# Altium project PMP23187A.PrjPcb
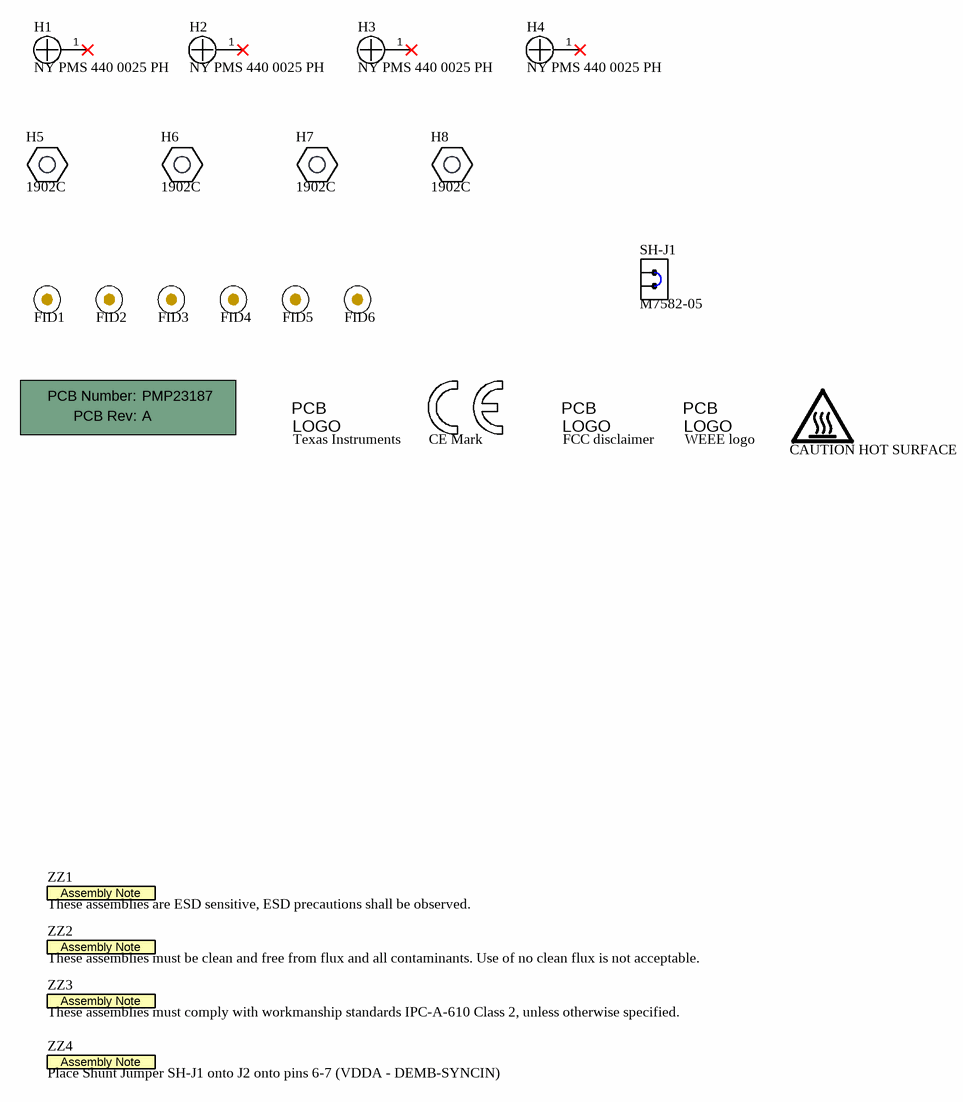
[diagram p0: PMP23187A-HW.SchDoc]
CopyrightYear: 2021; PCB_Layout: K Nielson; PCB_Rev: A; PRJ_Customer: Public Release; PRJ_Engineer: T Hegarty; PRJ_Number: PMP23187; PRJ_Title: LM5143Q-250W; SCH_Rev: A; TechSupport: http://www.ti.com/support; TID: N/A
2 sheets, 122 parts. Net scope: global (net labels, ports and power ports of the same name join across sheets).
Board file: PMP23187A.PcbDoc
Sheets:
  PMP23187A-HW.SchDoc
  PMP23187A-SCH.SchDoc

## Sheet PMP23187A-HW.SchDoc: LM5143Q-250W Hardware
size 431 x 279 mm; Date: Not shown in title block; ApprovedBy: Not shown in title block; CheckedBy: Not shown in title block; Author: Not shown in title block; CompanyName: Not shown in title block; DrawnBy: K Nielson; Engineer: Not shown in title block; Organization: Not shown in title block; Address1: Not shown in title block; Address2: Not shown in title block; Address3: Not shown in title block; Address4: Not shown in title block; DocumentNumber: 1; Revision: Use project parameter SCH_Rev; SheetNumber: 1; SheetTotal: 2; PageSetup: Record=PageOptions¦CenterHorizontal=True¦CenterVertical=True¦PrintScale=1.00¦XCorrection=1.00¦YCorrection=1.00¦PrintKind=0¦BorderSize=5000000¦LeftOffset=0¦BottomOffset=0¦Orientation=2¦PaperLength=1000¦PaperWidth=1000¦Scale=100¦PaperSource=15¦PrintQuality=600¦MediaType=1¦DitherType=10¦PaperKind=Letter¦PrintScaleMode=1

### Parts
!PCB1  Printed Circuit Board  (value not drawn)  (mechanical)
FID1  Fiducial  [Fiducial10-20]  (value not drawn)
FID2  Fiducial  [Fiducial10-20]  (value not drawn)
FID3  Fiducial  [Fiducial10-20]  (value not drawn)
FID4  Fiducial  [Fiducial10-20]  (value not drawn)
FID5  Fiducial  [Fiducial10-20]  (value not drawn)
FID6  Fiducial  [Fiducial10-20]  (value not drawn)
H1  NY PMS 440 0025 PH  [NY PMS 440 0025 PH]
H2  NY PMS 440 0025 PH  [NY PMS 440 0025 PH]
H3  NY PMS 440 0025 PH  [NY PMS 440 0025 PH]
H4  NY PMS 440 0025 PH  [NY PMS 440 0025 PH]
H5  1902C  [Keystone_1902C]
H6  1902C  [Keystone_1902C]
H7  1902C  [Keystone_1902C]
H8  1902C  [Keystone_1902C]
Logo1  CE Mark  [CE_Mark_5mm]  (no BOM)
Logo2  CAUTION HOT SURFACE  [IEC_HotSurface_Small]  (no BOM)
Logo3  Texas Instruments  [TI_Stacked_Overlay_Small]  (no BOM)
Logo4  FCC disclaimer  [FCC_disclaimer]  (no BOM)
Logo5  WEEE logo  [WEEE_Minimum]  (no BOM)
SH-J1  M7582-05  [Harwin_M7582-05]
ZZ1  These assemblies are ESD sensitive, ESD precautions shall be observed.  [AssemblyNote]  (no BOM)
ZZ2  These assemblies must be clean and free from flux and all contaminants. Use of no clean flux is not acceptable.  [AssemblyNote]  (no BOM)
ZZ3  These assemblies must comply with workmanship standards IPC-A-610 Class 2, unless otherwise specified.  [AssemblyNote]  (no BOM)
ZZ4  Place Shunt Jumper SH-J1 onto J2 onto pins 6-7 (VDDA - DEMB-SYNCIN)  [AssemblyNote]  (no BOM)

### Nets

Not connected (* = marked no-connect by the designer): H1 1*; H2 1*; H3 1*; H4 1*

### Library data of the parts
!PCB1 = CMP-0003618-2: Manufacturer: Any; PartNumber: PMP23187
FID1-FID6 = CMP-0077181-1: Fiducial mark.  There is nothing to buy or mount.
H1-H4 = CMP-0003617-1: Machine Screw, Round, #4-40 x 1/4, Nylon, Philips panhead; Manufacturer: B&F Fastener Supply; CompType: Hardware
H5-H8 = CMP-0003610-1: Standoff, Hex, 0.5"L #4-40 Nylon; Manufacturer: Keystone; CompType: Hardware
Logo1 = CMP-0074844-1: SymbolCreator: a0412235
Logo2 = CMP-0074837-2: IEC 61010-1 Hot Surface Warning; Manufacturer: Texas Instruments; SymbolCreator: a0412235; AEC Category: Q200; CompType: IC
Logo3 = CMP-0074838-1: Texas Instrument Corporate Signature; SymbolCreator: a0412235; Lib Reference: TI_Logo; Library Reference: Logo
Logo4 = CMP-0074847-1: FCC_disclaimer; Library Reference: Logo
Logo5 = CMP-0074769-1
SH-J1 = CMP-0078738-1: Single Operation 2.54mm Pitch Open Top Jumper Socket; Manufacturer: Harwin; CompType: Shunt
ZZ1 = CMP-0077236-1
ZZ2 = CMP-0077237-1
ZZ3 = CMP-0077238-1
ZZ4 = CMP-0077238-1: Place Shunt Jumper SH-J1 onto J2 pins VDDA - DEMB

## Sheet PMP23187A-SCH.SchDoc: LM5143Q-250W Schematic
size 431 x 279 mm; Date: Not shown in title block; ApprovedBy: Not shown in title block; CheckedBy: Not shown in title block; Author: Not shown in title block; CompanyName: Not shown in title block; DrawnBy: K Nielson; Engineer: Not shown in title block; Organization: Not shown in title block; Address1: Not shown in title block; Address2: Not shown in title block; Address3: Not shown in title block; Address4: Not shown in title block; DocumentNumber: 2; Revision: Use project parameter SCH_Rev; SheetNumber: 2; SheetTotal: 2; PageSetup: Record=PageOptions¦CenterHorizontal=True¦CenterVertical=True¦PrintScale=0.96¦XCorrection=1.00¦YCorrection=1.00¦PrintKind=0¦BorderSize=5000000¦LeftOffset=0¦BottomOffset=0¦Orientation=2¦PaperLength=1000¦PaperWidth=1000¦Scale=100¦PaperSource=7¦PrintQuality=600¦MediaType=1¦DitherType=10¦PaperKind=11" x 17"¦PrintScaleMode=1
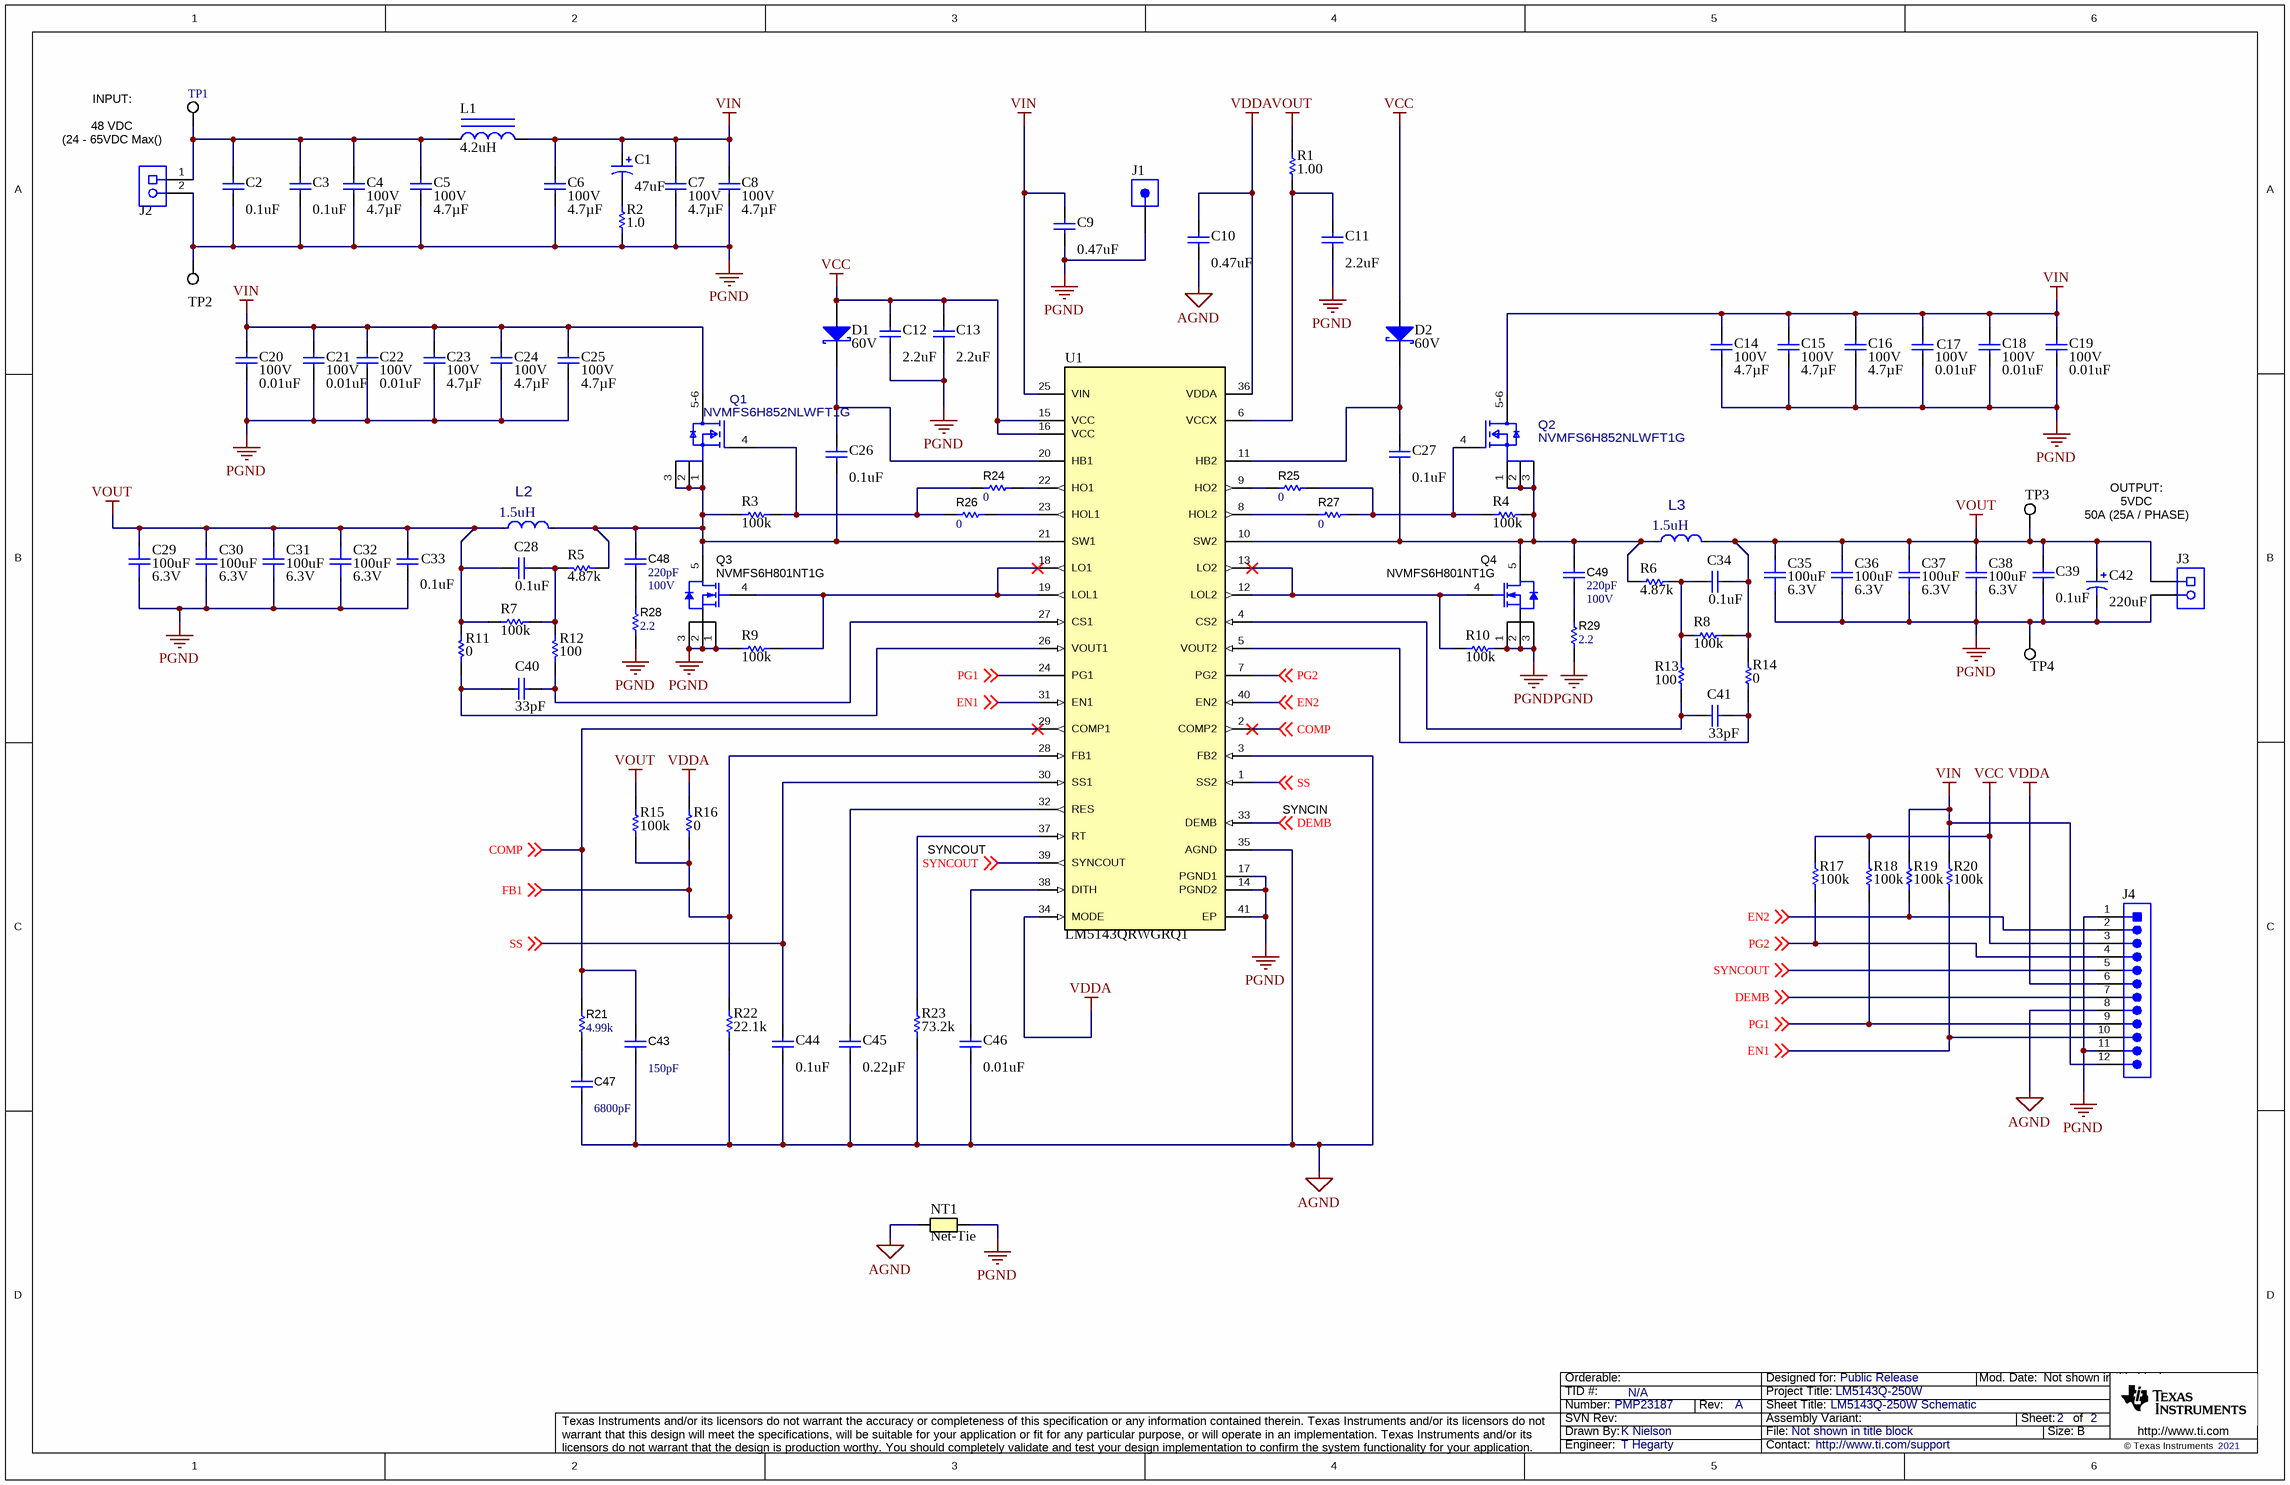
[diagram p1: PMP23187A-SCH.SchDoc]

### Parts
C1  ValueDisplayed: 47uF  [SM_RADIAL_G]  (hidden comment: EEE-FC1H470P)
C2  ValueDisplayed: 0.1uF  [0805_HV]  (hidden comment: C0805C104K1RACTU)
C3  ValueDisplayed: 0.1uF  [0805_HV]  (hidden comment: C0805C104K1RACTU)
C4  VDC_V: 100V  ValueDisplayed: 4.7µF  [1210_220]  (hidden comment: GCM32DC72A475KE02L)
C5  VDC_V: 100V  ValueDisplayed: 4.7µF  [1210_220]  (hidden comment: GCM32DC72A475KE02L)
C6  VDC_V: 100V  ValueDisplayed: 4.7µF  [1210_220]  (hidden comment: GCM32DC72A475KE02L)
C7  VDC_V: 100V  ValueDisplayed: 4.7µF  [1210_220]  (hidden comment: GCM32DC72A475KE02L)
C8  VDC_V: 100V  ValueDisplayed: 4.7µF  [1210_220]  (hidden comment: GCM32DC72A475KE02L)
C9  ValueDisplayed: 0.47uF  [0805L]  (hidden comment: GRM21BR72A474KA73L)
C10  ValueDisplayed: 0.47uF  [0603L]  (hidden comment: GCM188R71C474KA55D)
C11  ValueDisplayed: 2.2uF  [0603L]  (hidden comment: GRM188R71A225KE15D)
C12  ValueDisplayed: 2.2uF  [0603L]  (hidden comment: GRM188R71A225KE15D)
C13  ValueDisplayed: 2.2uF  [0603L]  (hidden comment: GRM188R71A225KE15D)
C14  VDC_V: 100V  ValueDisplayed: 4.7µF  [1210_220]  (hidden comment: GCM32DC72A475KE02L)
C15  VDC_V: 100V  ValueDisplayed: 4.7µF  [1210_220]  (hidden comment: GCM32DC72A475KE02L)
C16  VDC_V: 100V  ValueDisplayed: 4.7µF  [1210_220]  (hidden comment: GCM32DC72A475KE02L)
C17  VDC_V: 100V  ValueDisplayed: 0.01uF  [0402S]  (hidden comment: CGA2B3X7S2A103K050BB)
C18  VDC_V: 100V  ValueDisplayed: 0.01uF  [0402S]  (hidden comment: CGA2B3X7S2A103K050BB)
C19  VDC_V: 100V  ValueDisplayed: 0.01uF  [0402S]  (hidden comment: CGA2B3X7S2A103K050BB)
C20  VDC_V: 100V  ValueDisplayed: 0.01uF  [0402S]  (hidden comment: CGA2B3X7S2A103K050BB)
C21  VDC_V: 100V  ValueDisplayed: 0.01uF  [0402S]  (hidden comment: CGA2B3X7S2A103K050BB)
C22  VDC_V: 100V  ValueDisplayed: 0.01uF  [0402S]  (hidden comment: CGA2B3X7S2A103K050BB)
C23  VDC_V: 100V  ValueDisplayed: 4.7µF  [1210_220]  (hidden comment: GCM32DC72A475KE02L)
C24  VDC_V: 100V  ValueDisplayed: 4.7µF  [1210_220]  (hidden comment: GCM32DC72A475KE02L)
C25  VDC_V: 100V  ValueDisplayed: 4.7µF  [1210_220]  (hidden comment: GCM32DC72A475KE02L)
C26  ValueDisplayed: 0.1uF  [0603L]  (hidden comment: CGA3E2X7R1E104K080AA)
C27  ValueDisplayed: 0.1uF  [0603L]  (hidden comment: CGA3E2X7R1E104K080AA)
C28  ValueDisplayed: 0.1uF  [0603L]  (hidden comment: CGA3E2X7R1E104K080AA)
C29  ValueDisplayed: 100uF  VDC_V: 6.3V  [FP-GRM32EE70J107ME15L_1210-MFG]  (hidden comment: GRM32EE70J107ME15L)
C30  ValueDisplayed: 100uF  VDC_V: 6.3V  [FP-GRM32EE70J107ME15L_1210-MFG]  (hidden comment: GRM32EE70J107ME15L)
C31  ValueDisplayed: 100uF  VDC_V: 6.3V  [FP-GRM32EE70J107ME15L_1210-MFG]  (hidden comment: GRM32EE70J107ME15L)
C32  ValueDisplayed: 100uF  VDC_V: 6.3V  [FP-GRM32EE70J107ME15L_1210-MFG]  (hidden comment: GRM32EE70J107ME15L)
C33  ValueDisplayed: 0.1uF  [0603L]  (hidden comment: GRM188R72A104KA35D)
C34  ValueDisplayed: 0.1uF  [0603L]  (hidden comment: CGA3E2X7R1E104K080AA)
C35  ValueDisplayed: 100uF  VDC_V: 6.3V  [FP-GRM32EE70J107ME15L_1210-MFG]  (hidden comment: GRM32EE70J107ME15L)
C36  ValueDisplayed: 100uF  VDC_V: 6.3V  [FP-GRM32EE70J107ME15L_1210-MFG]  (hidden comment: GRM32EE70J107ME15L)
C37  ValueDisplayed: 100uF  VDC_V: 6.3V  [FP-GRM32EE70J107ME15L_1210-MFG]  (hidden comment: GRM32EE70J107ME15L)
C38  ValueDisplayed: 100uF  VDC_V: 6.3V  [FP-GRM32EE70J107ME15L_1210-MFG]  (hidden comment: GRM32EE70J107ME15L)
C39  ValueDisplayed: 0.1uF  [0603L]  (hidden comment: CGA3E2X7R1E104K080AA)
C40  ValueDisplayed: 33pF  [0603L]  (hidden comment: 06031A330JAT2A)
C41  ValueDisplayed: 33pF  [0603L]  (hidden comment: 06031A330JAT2A)
C42  ValueDisplayed: 220uF  [7343-31]  (hidden comment: T598D227M010ATE025)
C43  ValueDisplayed: 150pF  [0603L]  (hidden comment: 06035A151JAT2A)
C44  ValueDisplayed: 0.1uF  [0603L]  (hidden comment: CGA3E2X7R1E104K080AA)
C45  ValueDisplayed: 0.22µF  [0603L]  (hidden comment: CL10B224KO8VPNC)
C46  ValueDisplayed: 0.01uF  [0603L]  (hidden comment: GRM188R72A103KA01D)
C47  ValueDisplayed: 6800pF  [0603L]  (hidden comment: GRM1885C1H682JA01D)
C48  Cap_F: 220pF  VDC_V: 100V  [0603_HV]  (hidden comment: 06031C221KAT2A)
C49  Cap_F: 220pF  VDC_V: 100V  [0603_HV]  (hidden comment: 06031C221KAT2A)
D1  60V  [SOD-323F]
D2  60V  [SOD-323F]
J1  1040  [CONN_1040]  (value not drawn)
J2  1714971  [Phoenix_1714971]  (value not drawn)
J3  EM292902-UL  [Eaton_EM292902]  (value not drawn)
J4  TSW-112-07-G-S  [TSW-112-07-G-S]  (value not drawn)
L1  ValueDisplayed: 4.2uH  [WE-HC6]  (hidden comment: 744325420)
L2  value 1.5uH  [FP-VCUD128T-1R5M58_SMD2-MFG]  (hidden comment: VCUD128T-1R5M58)
L3  value 1.5uH  [FP-VCUD128T-1R5M58_SMD2-MFG]  (hidden comment: VCUD128T-1R5M58)
NT1  Net-Tie  [Net-Tie_10mil]  (net tie, no BOM)
Q1  NVMFS6H852NLWFT1G  [FP-NVMFS6H852NLWFT1G_DFN5-MFG]
Q2  NVMFS6H852NLWFT1G  [FP-NVMFS6H852NLWFT1G_DFN5-MFG]
Q3  NVMFS6H801NT1G  [SO-8FL]
Q4  NVMFS6H801NT1G  [SO-8FL]
R1  ValueDisplayed: 1.00  [0603L]  (hidden comment: RC0603FR-071RL)
R2  ValueDisplayed: 1.0  [1206]  (hidden comment: CRCW12061R00JNEA)
R3  ValueDisplayed: 100k  [0603L]  (hidden comment: CRCW0603100KFKEA)
R4  ValueDisplayed: 100k  [0603L]  (hidden comment: CRCW0603100KFKEA)
R5  ValueDisplayed: 4.87k  [0603L]  (hidden comment: RC0603FR-074K87L)
R6  ValueDisplayed: 4.87k  [0603L]  (hidden comment: RC0603FR-074K87L)
R7  ValueDisplayed: 100k  [0603L]  (hidden comment: CRCW0603100KFKEA)
R8  ValueDisplayed: 100k  [0603L]  (hidden comment: CRCW0603100KFKEA)
R9  ValueDisplayed: 100k  [0603L]  (hidden comment: CRCW0603100KFKEA)
R10  ValueDisplayed: 100k  [0603L]  (hidden comment: CRCW0603100KFKEA)
R11  ValueDisplayed: 0  [0603L]  (hidden comment: CRCW06030000Z0EA)
R12  ValueDisplayed: 100  [0603L]  (hidden comment: CRCW0603100RFKEA)
R13  ValueDisplayed: 100  [0603L]  (hidden comment: CRCW0603100RFKEA)
R14  ValueDisplayed: 0  [0603L]  (hidden comment: CRCW06030000Z0EA)
R15  ValueDisplayed: 100k  [0603L]  (hidden comment: CRCW0603100KFKEA)
R16  ValueDisplayed: 0  [0603L]  (hidden comment: CRCW06030000Z0EA)
R17  ValueDisplayed: 100k  [0603L]  (hidden comment: CRCW0603100KFKEA)
R18  ValueDisplayed: 100k  [0603L]  (hidden comment: CRCW0603100KFKEA)
R19  ValueDisplayed: 100k  [0603L]  (hidden comment: CRCW0603100KFKEA)
R20  ValueDisplayed: 100k  [0603L]  (hidden comment: CRCW0603100KFKEA)
R21  ValueDisplayed: 4.99k  [0603L]  (hidden comment: RC0603FR-074K99L)
R22  ValueDisplayed: 22.1k  [0603L]  (hidden comment: CRCW060322K1FKEA)
R23  ValueDisplayed: 73.2k  [0603L]  (hidden comment: RC0603FR-0773K2L)
R24  ValueDisplayed: 0  [0402L]  (hidden comment: ERJ-2GE0R00X)
R25  ValueDisplayed: 0  [0402L]  (hidden comment: ERJ-2GE0R00X)
R26  ValueDisplayed: 0  [0402L]  (hidden comment: ERJ-2GE0R00X)
R27  ValueDisplayed: 0  [0402L]  (hidden comment: ERJ-2GE0R00X)
R28  ValueDisplayed: 2.2  [0805_HV]  (hidden comment: ERJ-6GEYJ2R2V)
R29  ValueDisplayed: 2.2  [0805_HV]  (hidden comment: ERJ-6GEYJ2R2V)
TP1  5015  [Testpoint_Keystone_Miniature]  (value not drawn)
TP2  5015  [Testpoint_Keystone_Miniature]  (value not drawn)
TP3  5015  [Testpoint_Keystone_Miniature]  (value not drawn)
TP4  5015  [Testpoint_Keystone_Miniature]  (value not drawn)
U1  LM5143QRWGRQ1  [RWG0040A]

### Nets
AGND: C10.1 C43.2 C44.2 C45.2 C46.2 C47.2 J4.8 NT1.1 R22.1 R23.1 U1.3(FB2) U1.35(AGND)
PGND: C2.1 C3.2 C4.2 C5.2 C6.2 C7.2 C8.2 C9.1 C11.2 C12.2 C13.2 C14.2 C15.2 C16.2 C17.2 C18.2 C19.2 C20.2 C21.2 C22.2 C23.2 C24.2 C25.2 C29.1 C30.1 C31.1 C32.1 C33.2 C35.1 C36.1 C37.1 C38.1 C39.2 C42.2(-) J1.1 J2.2 J3.2 J4.1 J4.11 NT1.2 Q3.1(S) Q3.2(S) Q3.3(S) Q4.1(S) Q4.2(S) Q4.3(S) R2.1 R9.2 R10.1 R28.1 R29.1 TP2.1 TP4.1 U1.14(PGND2) U1.17(PGND1) U1.41(EP)
VCC: C12.1 C13.1 D1.2(A) D2.2(A) J4.3 R17.2 R18.2 U1.15(VCC) U1.16(VCC)
VDDA: C10.2 J4.6 R16.2 U1.34(MODE) U1.36(VDDA)
VIN: C1.1(+) C6.1 C7.1 C8.1 C9.2 C14.1 C15.1 C16.1 C17.1 C18.1 C19.1 C20.1 C21.1 C22.1 C23.1 C24.1 C25.1 J4.12 L1.2 Q1.5-6(D) Q2.5-6(D) R19.2 R20.2 U1.25(VIN)
VOUT: C28.2 C29.2 C30.2 C31.2 C32.2 C33.1 C34.2 C35.2 C36.2 C37.2 C38.2 C39.1 C42.1(+) J3.1 L2.1 L3.2 R1.2 R7.2 R8.1 R11.2 R14.2 R15.2 TP3.1
COMP: C43.1 R21.2 U1.2(COMP2) U1.29(COMP1) ; off-sheet COMP
DEMB: J4.7 U1.33(DEMB) ; off-sheet DEMB
EN1: J4.10 R20.1 U1.31(EN1) ; off-sheet EN1
EN2: J4.2 R19.1 U1.40(EN2) ; off-sheet EN2
FB1: R15.1 R16.1 R22.2 U1.28(FB1) ; off-sheet FB1
PG1: J4.9 R18.1 U1.24(PG1) ; off-sheet PG1
PG2: J4.4 R17.1 U1.7(PG2) ; off-sheet PG2
SS: C44.1 U1.1(SS2) U1.30(SS1) ; off-sheet SS
SYNCOUT: J4.5 U1.39(SYNCOUT) ; off-sheet SYNCOUT
NetC1_2: C1.2(-) R2.2
NetC2_2: C2.2 C3.1 C4.1 C5.1 J2.1 L1.1 TP1.1
NetC11_1: C11.1 R1.1 U1.6(VCCX)
NetC26_1: C26.1 C48.1 L2.2 Q1.1(S) Q1.2(S) Q1.3(S) Q3.5(D) R3.2 R5.2 U1.21(SW1)
NetC26_2: C26.2 D1.1(K) U1.20(HB1)
NetC27_1: C27.1 C49.1 L3.1 Q2.1(S) Q2.2(S) Q2.3(S) Q4.5(D) R4.1 R6.2 U1.10(SW2)
NetC27_2: C27.2 D2.1(K) U1.11(HB2)
NetC28_1: C28.1 R5.1 R7.1 R12.2
NetC34_1: C34.1 R6.1 R8.2 R13.2
NetC40_1: C40.1 R11.1 U1.26(VOUT1)
NetC40_2: C40.2 R12.1 U1.27(CS1)
NetC41_1: C41.1 R14.1 U1.5(VOUT2)
NetC41_2: C41.2 R13.1 U1.4(CS2)
NetC45_1: C45.1 U1.32(RES)
NetC46_1: C46.1 U1.38(DITH)
NetC47_1: C47.1 R21.1
NetC48_2: C48.2 R28.2
NetC49_2: C49.2 R29.2
NetQ1_4: Q1.4(G) R3.1 R24.1 R26.1
NetQ2_4: Q2.4(G) R4.2 R25.2 R27.2
NetQ3_4: Q3.4(G) R9.1 U1.18(LO1) U1.19(LOL1)
NetQ4_4: Q4.4(G) R10.2 U1.12(LOL2) U1.13(LO2)
NetR23_2: R23.2 U1.37(RT)
NetR24_2: R24.2 U1.22(HO1)
NetR25_1: R25.1 U1.9(HO2)
NetR26_2: R26.2 U1.23(HOL1)
NetR27_1: R27.1 U1.8(HOL2)

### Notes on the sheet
- INPUT:
- 48 VDC
- (24 - 65VDC Max()
- 5VDC
- OUTPUT:
- 50A (25A / PHASE)
- SYNCIN
- SYNCOUT

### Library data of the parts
C1 = CMP-0011173-2: CAP, AL, 47 uF, 50 V, +/- 20%, 0.3 ohm, SMD; Manufacturer: Panasonic; TaMin_C: -40°C; ESR_ohm: 3d; Polarized: Y; SizeAreaWB_mm2: 172.2; Value1: 0.3 ohm; U/M: EA; Value: 47uF; TaMax_C: 105°C; SizeZ_mm: 10.2; SizeX_mm: 12; SizeY_mm: 10.3; Cap_Case: G; Value2: 50V; SizeArea_mm2: 123.6; CompType: Capacitor; Cap_F: 47µF; IRMS_A: 5dA; AEC Category: Q200
C2 C3 = CMP-0007722-2: CAP, CERM, 0.1 uF, 100 V, +/- 10%, X7R, 0805; Manufacturer: Kemet; TaMin_C: -55°C; ESR_ohm: 0.064; Polarized: N; SizeAreaWB_mm2: 6.75; Value1: 0.064 ohm; U/M: EA; Value: 0.1uF; TaMax_C: 125°C; SizeZ_mm: 1.45; SizeX_mm: 2; SizeY_mm: 1.25; Cap_Case: 0805; Value2: 100V; SizeArea_mm2: 2.5; CompType: Capacitor; Cap_F: 100nF; IRMS_A: 1.64A; AEC Category: Q200
C4-C8 C14-C16 C23-C25 = CMP-0082268-1: CAP, CERM, 4.7 µF, 100 V,+/- 10%, X7S, AEC-Q200 Grade 1, 1210; Manufacturer: MuRata; TaMin_C: -55°C; ESR_ohm: 1m; Polarized: N; SizeAreaWB_mm2: 14.7; Value1: 0.001 ohm; U/M: EA; Value: 4.7uF; TaMax_C: 125°C; SizeZ_mm: 2.2; SizeX_mm: 3.2; SizeY_mm: 2.5; Cap_Case: 1210; SizeArea_mm2: 8; AEC Qualified: Y; IRMS_A: 6A; AEC Grade: 1; AEC Category: Q200
C9 = CMP-0008374-2: CAP, CERM, 0.47 uF, 100 V, +/- 10%, X7R, 0805; Manufacturer: MuRata; TaMin_C: -55°C; Polarized: N; SizeAreaWB_mm2: 6.75; Value1: Unknown; U/M: EA; Value: 0.47uF; TaMax_C: 125°C; SizeZ_mm: 1.45; SizeX_mm: 2; SizeY_mm: 1.25; Cap_Case: 0805; Value2: 100V; SizeArea_mm2: 2.5; CompType: Capacitor; Cap_F: 470nF; AEC Category: Q200
C10 = CMP-0007138-4: CAP, CERM, 0.47 uF, 16 V, +/- 10%, X7R, AEC-Q200 Grade 1, 0603; Manufacturer: MuRata; TaMin_C: -55°C; Polarized: N; SizeAreaWB_mm2: 4.68; Value1: Unknown; U/M: EA; Value: 0.47uF; TaMax_C: 125°C; SizeZ_mm: 1; SizeX_mm: 1.6; SizeY_mm: 0.8; Cap_Case: 0603; Value2: 16V; SizeArea_mm2: 1.28; CompType: Capacitor; AEC Qualified: Y; Cap_F: 470nF; AEC Category: Q200
C11 = CMP-0007370-4: CAP, CERM, 2.2 uF, 10 V, +/- 10%, X7R, 0603; Manufacturer: MuRata; TaMin_C: -55°C; Polarized: N; SizeAreaWB_mm2: 4.68; Value1: 0.009 ohm; U/M: EA; Value: 2.2uF; TaMax_C: 125°C; SizeZ_mm: 1; SizeX_mm: 1.6; SizeY_mm: 0.8; Cap_Case: 0603; Value2: 10V; SizeArea_mm2: 1.28; CompType: Capacitor; Cap_F: 2.2µF; AEC Category: Q200; ESR_ohm: 9m
C12 C13 = CMP-0007370-4: CAP, CERM, 2.2 uF, 10 V, +/- 10%, X7R, 0603; Manufacturer: MuRata; TaMin_C: -55°C; ESR_ohm: 9m; Polarized: N; SizeAreaWB_mm2: 4.68; Value1: 0.009 ohm; U/M: EA; Value: 2.2uF; TaMax_C: 125°C; SizeZ_mm: 1; SizeX_mm: 1.6; SizeY_mm: 0.8; Cap_Case: 0603; Value2: 10V; SizeArea_mm2: 1.28; CompType: Capacitor; Cap_F: 2.2µF; AEC Category: Q200
C17-C22 = CMP-0006333-2: CAP, CERM, 0.01 uF, 100 V, +/- 10%, X7S, AEC-Q200 Grade 1, 0402; Manufacturer: TDK; TaMin_C: -55°C; ESR_ohm: 0.4102; Polarized: N; SizeAreaWB_mm2: 3; Value1: 0.410191 ohm; U/M: EA; Value: 0.01uF; TaMax_C: 125°C; SizeZ_mm: 0.6; SizeX_mm: 1; SizeY_mm: 0.5; Cap_Case: 0402; AEC Qualified: Y; Cap_F: 10nF; IRMS_A: 291.729mA; AEC Category: Q200
C26 C27 C39 C44 = CMP-0007077-5: CAP, CERM, 0.1 uF, 25 V, +/- 10%, X7R, AEC-Q200 Grade 1, 0603; Manufacturer: TDK; TaMin_C: -55°C; Polarized: N; SizeAreaWB_mm2: 4.68; Value1: Unknown; U/M: EA; Value: 0.1uF; TaMax_C: 125°C; SizeZ_mm: 1; SizeX_mm: 1.6; SizeY_mm: 0.8; Cap_Case: 0603; Value2: 25V; SizeArea_mm2: 1.28; AEC Qualified: Y; Cap_F: 100nF; AEC Category: Q200
C28 C34 = CMP-0007077-5: CAP, CERM, 0.1 uF, 25 V, +/- 10%, X7R, AEC-Q200 Grade 1, 0603; Manufacturer: TDK; TaMin_C: -55°C; Polarized: N; SizeAreaWB_mm2: 4.68; Value1: Unknown; U/M: EA; Value: 0.1uF; TaMax_C: 125°C; SizeZ_mm: 1; SizeX_mm: 1.6; SizeY_mm: 0.8; Cap_Case: 0603; Value2: 25V; SizeArea_mm2: 1.28; CompType: Capacitor; AEC Qualified: Y; Cap_F: 100nF; AEC Category: Q200
C29-C32 C35-C38 = CMP-0093793-1: Chip Multilayer Ceramic Capacitors for General Purpose, 1210, 100uF, X7U, +22%/-56%, 20%, 6.3V; Manufacturer: Murata; SizeZ_mm: 2.7mm; Cap_F: 100µF; Value: 100µF; AEC Qualified: No
C33 = CMP-0007469-4: CAP, CERM, 0.1 uF, 100 V, +/- 10%, X7R, 0603; Manufacturer: MuRata; TaMin_C: -55°C; Polarized: N; SizeAreaWB_mm2: 4.68; Value1: Unknown; U/M: EA; Value: 0.1uF; TaMax_C: 125°C; SizeZ_mm: 1; SizeX_mm: 1.6; SizeY_mm: 0.8; Cap_Case: 0603; Value2: 100V; SizeArea_mm2: 1.28; CompType: Capacitor; Cap_F: 100nF; AEC Category: Q200
C40 C41 = CMP-0006722-4: CAP, CERM, 33 pF, 100 V, +/- 5%, C0G/NP0, 0603; Manufacturer: AVX; TaMin_C: -55°C; ESR_ohm: 2.09d; Polarized: N; SizeAreaWB_mm2: 4.68; Value1: 0.209 ohm; U/M: EA; Value: 33pF; TaMax_C: 125°C; SizeZ_mm: 1; SizeX_mm: 1.6; SizeY_mm: 0.8; Cap_Case: 0603; Value2: 100V; SizeArea_mm2: 1.28; CompType: Capacitor; AEC Category: Q200
C42 = CMP-0012661-3: CAP, Tantalum Polymer, 220 uF, 10 V, +/- 20%, 0.025 ohm, AEC-Q200 Grade 1, 7343-31 SMD; Manufacturer: Kemet; TaMin_C: -55°C; ESR_ohm: 0.025; Polarized: Y; SizeAreaWB_mm2: 58.59; Value: 220uF; TaMax_C: 125°C; SizeZ_mm: 3.1; SizeX_mm: 7.3; SizeY_mm: 4.3; Cap_Case: 7.3x4.3x3.1mm; Value2: 10V; SizeArea_mm2: 31.39; CompType: Capacitor; Cap_F: 220µF; IRMS_A: 3A; AEC Grade: 1; AEC Category: Q200
C43 = CMP-0006768-4: CAP, CERM, 150 pF, 50 V, +/- 5%, C0G/NP0, 0603; Manufacturer: AVX; TaMin_C: -55°C; Polarized: N; SizeAreaWB_mm2: 4.68; Value1: 0.098 ohm; U/M: EA; Value: 150pF; TaMax_C: 125°C; SizeZ_mm: 1; SizeX_mm: 1.6; SizeY_mm: 0.8; Cap_Case: 0603; Value2: 50V; SizeArea_mm2: 1.28; AEC Category: Q200; ESR_ohm: 98m
C45 = CMP-0080102-1: CAP, CERM, 0.22 µF, 16 V,+/- 10%, X7R, AEC-Q200 Grade 1, 0603; Manufacturer: Samsung; TaMin_C: -55°C; Polarized: N; SizeAreaWB_mm2: 4.68; U/M: EA; Value: 0.22uF; TaMax_C: 125°C; SizeZ_mm: 1; SizeX_mm: 1.6; SizeY_mm: 0.8; Cap_Case: 0603; Value2: 16V; SizeArea_mm2: 1.28; CompType: Capacitor; AEC Qualified: Y; Cap_F: 220nF; AEC Category: Q200
C46 = CMP-0007468-5: CAP, CERM, 0.01 uF, 100 V, +/- 10%, X7R, 0603; Manufacturer: MuRata; TaMin_C: -55°C; Polarized: N; SizeAreaWB_mm2: 4.68; Value1: Unknown; U/M: EA; Value: 0.01uF; TaMax_C: 125°C; SizeZ_mm: 1; SizeX_mm: 1.6; SizeY_mm: 0.8; Cap_Case: 0603; Value2: 100V; SizeArea_mm2: 1.28; CompType: Capacitor; Cap_F: 10nF; AEC Category: Q200
C47 = CMP-0078296-1: CAP, CERM, 6800 pF, 50 V,+/- 5%, C0G/NP0, 0603; Manufacturer: MuRata; TaMin_C: -55°C; Polarized: N; SizeAreaWB_mm2: 4.68; U/M: EA; Value: 6800pF; TaMax_C: 125°C; SizeZ_mm: 1; SizeX_mm: 1.6; SizeY_mm: 0.8; Cap_Case: 0603; Value2: 50V; SizeArea_mm2: 1.28; Cap_F: 6.8nF; AEC Category: Q200
C48 C49 = CMP-0006735-1: CAP, CERM, 220 pF, 100 V, +/- 10%, X7R, 0603; Manufacturer: AVX; TaMin_C: -55°C; ESR_ohm: 0.579; Polarized: N; SizeAreaWB_mm2: 4.68; Value1: 0.579 ohm; U/M: EA; Value: 220pF; TaMax_C: 125°C; SizeZ_mm: 1; SizeX_mm: 1.6; SizeY_mm: 0.8; Cap_Case: 0603; SizeArea_mm2: 1.28; AEC Category: Q200
D1 D2 = CMP-0077011-2: Diode, Schottky, 60 V, 1 A, SOD-323F; PartNumber: PMEG6010CEJ,115; Manufacturer: Nexperia; SizeAreaWB_mm2: 7.875; SizeArea_mm2: 3.125; TJmax_C: 150°C; AEC Category: Q101; SizeZ_mm: 0.8; Green_REACh: Incomplete; Io_A: 1A; Vf_V: 660mV; SizeY_mm: 1.25; Value2: 0.66V; Green_Lifecycle: Not Set; SizeX_mm: 2.5
J1 = CMP-0055161-1: TEST POINT SLOTTED .118", TH; Manufacturer: Keystone; CNHeader: FALSE; Green_Lifecycle: Active; Green_REACh: Passed; CT: TRUE
J2 = CMP-0055554-1: Receptacle, 9.52mm, 2x1, TH; Manufacturer: Phoenix Contact; CNHeader: FALSE; Current_A: 32A; Gender: Female; Cert_CSA: Y; Voltage_V: 1kV; Row_Count: 1; Pitch_mm: 9.52
J3 = CMP-0077513-2: Terminal Block, 10.16mm, 2x1, Tin, R/A, TH; Manufacturer: Eaton; Pitch_mm: 10.16; Gender: Female; Voltage_V: 300V; Current_A: 65A; Cert_CULUS: Y; Row_Count: 1
J4 = CMP-0075424-1: Header, 100mil, 12x1, Gold, TH; Manufacturer: Samtec; Pitch_mm: 2.54; Cert_VDE: N; Gender: Male; Cert_CSA: Y; Current_A: 6.3A; Voltage_V: 550V; CT: False; Row_Count: 1; CNHeader: True
L1 = CMP-0063966-1: Inductor, Shielded Drum Core, Superflux, 4.2 uH, 11 A, 0.0068 ohm, SMD; Manufacturer: Wurth Elektronik; Isat: 14A @ 30% inductance drop; Irms: 11A @ 50C rise; Green_Lifecycle: Active; SizeAreaWB_mm2: 158.6; DCR_ohm: 6.8m; Green_REACh: Passed; Value: 4.2uH; Imax_A: 11A; SizeZ_mm: 5; SizeX_mm: 11; SizeY_mm: 10.2; SizeArea_mm2: 112.2; Ind_H: 4.2µH; AEC Category: Q200
L2 L3 = CMP-0094401-1: Inductor 1.5uH 1.6mOhm 32.5A; Manufacturer: Cyntec; AEC Qualified: No; SizeZ_mm: 0.3mm; Ind_H: 1.5µH; DCR_ohm: 1.6m; Isat: 46.7A
NT1 = CMP-0078142-4: Single point connection between nets.
Q1 Q2 = CMP-0092446-1: N-Channel 11A (Ta), 42A (Tc) 3.6W (Ta), 54W (Tc) Surface Mount 5-DFN (5x6) (8-SOFL); Manufacturer: ON Semiconductor; Rthja Max: 42°C/W; Drain To Source Breakdown Voltage: 80V; AEC Grade: Grade 0; Transconductance: 55S; Turn On Delay Time: 29ns; VdsMax_V: 1.2V; Typ Forward Diode Voltage: 0.81V; QgTyp_nC: 17nC @ 10V; Reverse Recovery Charge: 25nC; Turn Off Delay Time: 18ns; TJmax_C: +175°C; AEC Qualified: Yes; Reverse Recovery Time: 32ns; Input Capacitace At Vds: 906pF @ 40V; Standoff Height: 0mm; Threshold Vgs Max: 2V; Rdson45_ohm: 13.4m; Vgs_V: 20V; SizeZ_mm: 1.1mm; Number Of Channels: 1; ChMode: False; Pulse Drain Current: 208A
Q3 Q4 = CMP-0750157-1: MOSFET, N-CH, 80 V, 157 A, AEC-Q101, SO-8FL; Manufacturer: ON Semiconductor; Alternate Manufacturer: None; Value1: ? ohm; SizeZ_mm: 1.1; SizeY_mm: 5.15; ChType: N; AEC Qualified: Y; ChMode: Enhancement; VdsMax_V: 80V; SizeAreaWB_mm2: 58.2725; SizeX_mm: 6.15; Vgs_V: 20V; Value2: 64 nC; AEC Category: Q101; QgTyp_nC: 64; SizeArea_mm2: 31.6725; Value: 80V; IdsMax_A: 157A
R1 = CMP-0022900-4: RES, 1.00, 1%, 0.1 W, 0603; Manufacturer: Yageo; Power_W: 100mW; TempCo: 200 ppm/C; Value_Code: 1R00; Value: 1.00; EIA_Code: E96; Res_ohm: 1; SizeX_mm: 1.6; SizeY_mm: 0.8; Value2: 0.1W; SizeArea_mm2: 1.28; CompType: Resistor; AEC Qualified: N; VDC_V: 75V; AEC Category: Q200; SizeAreaWB_mm2: 4.68
R2 = CMP-0018617-3: RES, 1.0, 5%, 0.25 W, AEC-Q200 Grade 0, 1206; Manufacturer: Vishay-Dale; Power_W: 250mW; TempCo: 200 ppm/C; Value_Code: 1R00; Value: 1.0; EIA_Code: E24; Res_ohm: 1; SizeX_mm: 3.2; SizeY_mm: 1.6; SizeZ_mm: 1.35; Value2: 0.25W; SizeArea_mm2: 5.12; AEC Qualified: Y; VDC_V: 200V; AEC Category: Q200; AEC Grade: 0
R3 R4 R7-R10 R15 R17-R20 = CMP-0021990-4: RES, 100 k, 1%, 0.1 W, AEC-Q200 Grade 0, 0603; Manufacturer: Vishay-Dale; Power_W: 100mW; TempCo: 100 ppm/C; Value: 100k; EIA_Code: E96; SizeX_mm: 1.6; SizeY_mm: 0.8; SizeZ_mm: 1; Value2: 0.1W; SizeArea_mm2: 1.28; CompType: Resistor; AEC Qualified: Y; VDC_V: 75V; AEC Category: Q200; AEC Grade: 0
R5 R6 = CMP-0023154-5: RES, 4.87 k, 1%, 0.1 W, 0603; Manufacturer: Yageo; Power_W: 100mW; TempCo: 100 ppm/C; Value_Code: 4k87; Value: 4.87k; EIA_Code: E96; SizeX_mm: 1.6; SizeY_mm: 0.8; SizeZ_mm: 1; Value2: 0.1W; SizeArea_mm2: 1.28; AEC Qualified: N; VDC_V: 75V; AEC Category: Q200; SizeAreaWB_mm2: 4.68
R11 R14 = CMP-0025697-4: RES, 0, 5%, 0.1 W, AEC-Q200 Grade 0, 0603; Manufacturer: Vishay-Dale; Power_W: 100mW; TempCo: 200 ppm/C; Value_Code: 0000; Value: 0; EIA_Code: E24; SizeX_mm: 1.6; SizeY_mm: 0.8; SizeZ_mm: 1; Value2: 0.1W; SizeArea_mm2: 1.28; CompType: Resistor; AEC Qualified: Y; VDC_V: 75V; AEC Category: Q200
R12 R13 = CMP-0021991-4: RES, 100, 1%, 0.1 W, AEC-Q200 Grade 0, 0603; Manufacturer: Vishay-Dale; Power_W: 100mW; TempCo: 100 ppm/C; Value_Code: 100R; Value: 100; EIA_Code: E96; SizeX_mm: 1.6; SizeY_mm: 0.8; SizeZ_mm: 1; Value2: 0.1W; SizeArea_mm2: 1.28; AEC Qualified: Y; VDC_V: 75V; AEC Category: Q200; AEC Grade: 0
R16 = CMP-0025697-4: RES, 0, 5%, 0.1 W, AEC-Q200 Grade 0, 0603; Manufacturer: Vishay-Dale; Power_W: 100mW; TempCo: 200 ppm/C; Value_Code: 0000; Value: 0; EIA_Code: E24; SizeX_mm: 1.6; SizeY_mm: 0.8; SizeZ_mm: 1; Value2: 0.1W; SizeArea_mm2: 1.28; AEC Qualified: Y; VDC_V: 75V; AEC Category: Q200
R21 = CMP-0023155-5: RES, 4.99 k, 1%, 0.1 W, 0603; Manufacturer: Yageo; Power_W: 100mW; TempCo: 100 ppm/C; Value_Code: 4k99; Value: 4.99k; EIA_Code: E96; SizeX_mm: 1.6; SizeY_mm: 0.8; SizeZ_mm: 1; Value2: 0.1W; SizeArea_mm2: 1.28; AEC Qualified: N; VDC_V: 75V; AEC Category: Q200; SizeAreaWB_mm2: 4.68
R22 = CMP-0022220-4: RES, 22.1 k, 1%, 0.1 W, AEC-Q200 Grade 0, 0603; Manufacturer: Vishay-Dale; Power_W: 100mW; TempCo: 100 ppm/C; Value_Code: 22k1; Value: 22.1k; EIA_Code: E96; SizeX_mm: 1.6; SizeY_mm: 0.8; SizeZ_mm: 1; Value2: 0.1W; SizeArea_mm2: 1.28; CompType: Resistor; AEC Qualified: Y; VDC_V: 75V; AEC Category: Q200; AEC Grade: 0
R23 = CMP-0023263-5: RES, 73.2 k, 1%, 0.1 W, 0603; Manufacturer: Yageo; Power_W: 100mW; TempCo: 100 ppm/C; Value_Code: 73k2; Value: 73.2k; EIA_Code: E96; SizeX_mm: 1.6; SizeY_mm: 0.8; SizeZ_mm: 1; Value2: 0.1W; SizeArea_mm2: 1.28; AEC Qualified: N; VDC_V: 75V; AEC Category: Q200; SizeAreaWB_mm2: 4.68
R24-R27 = CMP-0026992-3: RES, 0, 5%, 0.1 W, AEC-Q200 Grade 0, 0402; Manufacturer: Panasonic; Power_W: 100mW; TempCo: 600 ppm/C; Value_Code: 0000; Value: 0; EIA_Code: E24; SizeX_mm: 1; SizeY_mm: 0.5; SizeZ_mm: 0.6; Value2: 0.1W; AEC Qualified: Y; VDC_V: 50V; AEC Category: Q200; SizeAreaWB_mm2: 3
R28 R29 = CMP-0020693-3: RES, 2.2, 5%, 0.125 W, AEC-Q200 Grade 0, 0805; Manufacturer: Panasonic; Power_W: 125mW; TempCo: 600 ppm/C; Value_Code: 2R20; Value: 2.2; EIA_Code: E24; SizeX_mm: 2; SizeY_mm: 1.25; SizeZ_mm: 1.45; Value2: 0.125W; SizeArea_mm2: 2.5; AEC Qualified: Y; VDC_V: 150V; AEC Category: Q200; AEC Grade: 0; SizeAreaWB_mm2: 6.75
TP1-TP4 = CMP-0055152-1: Test Point, Miniature, SMT; Manufacturer: Keystone; CNHeader: FALSE; Green_Lifecycle: Active; Green_REACh: Passed; CT: TRUE
U1 = CMP-0079128-2: 3.5-V to 65-V Low IQ, Dual Synchronous Buck DC-DC Controller, RWG0040A (VQFNP-40); Manufacturer: Texas Instruments; Alternate PartNumber: LM5143QRWGTQ1; SizeAreaWB_mm2: 64; SizeArea_mm2: 36; AEC Qualified: Y; AEC Category: Q200; SizeZ_mm: 0.9; SizeY_mm: 6; CompType: IC; Rating: Automotive

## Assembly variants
001: not fitted C40 FID1 FID2 FID3 FID4 FID5 FID6 R7 R8 R15 R22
